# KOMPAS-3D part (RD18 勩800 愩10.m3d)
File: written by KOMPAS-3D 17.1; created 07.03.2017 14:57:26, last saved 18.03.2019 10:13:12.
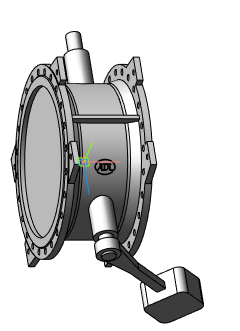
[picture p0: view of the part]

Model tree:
1. Операция без истории:2  (labels: Сталь 20  ГОСТ 1050-88)

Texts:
  RD18 Ду100 Ру16
  RD18 Ду150 Ру16
  RD18 Ду200 Ру16
  RD18 Ду250 Ру16
  RD18 Ду300 Ру16
  RD18 Ду350 Ру16
  RD18 Ду400 Ру10
  RD18 Ду400 Ру16
  RD18 Ду450 Ру10
  RD18 Ду450 Ру16
  RD18 Ду500 Ру10
  RD18 Ду500 Ру16
  RD18 Ду600 Ру10
  RD18 Ду600 Ру16
  RD18 Ду700 Ру10
  RD18 Ду700 Ру16
  RD18 Ду800 Ру10
  RD18 Ду800 Ру16
  RD18 Ду900 Ру10
  RD18 Ду900 Ру16
  RD18 Ду1000 Ру10
  RD18 Ду1000 Ру16
  RD18 Ду1200 Ру16
  RD18 Ду1400 Ру16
